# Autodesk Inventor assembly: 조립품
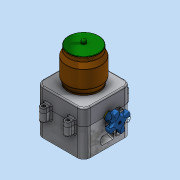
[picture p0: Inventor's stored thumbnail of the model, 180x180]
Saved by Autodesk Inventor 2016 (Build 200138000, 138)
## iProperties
Created: 2018-01
Part Number: 조립품
Material: 일반
Document SubType Name: Assembly
Designer: Administrator
Author: Administrator
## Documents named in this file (9)
- C:\Users\Administrator\Desktop\480108V1025\조립품.iam
- C:\Users\Administrator\Desktop\480108V1025\본체.ipt
- C:\Users\Administrator\Desktop\480108V1025\핸들축.ipt
- C:\Users\Administrator\Desktop\480108V1025\용기.ipt
- C:\Users\Administrator\Desktop\480108V1025\본체커버.ipt
- C:\Users\Administrator\Desktop\480108V1025\볼트 M4x12.ipt
- C:\Users\Administrator\Desktop\480108V1025\용기캡.ipt
- C:\Users\Administrator\Desktop\480108V1025\핸들.ipt
- C:\Users\Administrator\Desktop\480108V1025\볼트 M3x12.ipt
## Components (2 placed, 2 different names)
1. 핸들축:1
2. 핸들:1
